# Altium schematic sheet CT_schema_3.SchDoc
size 362 x 192 mm
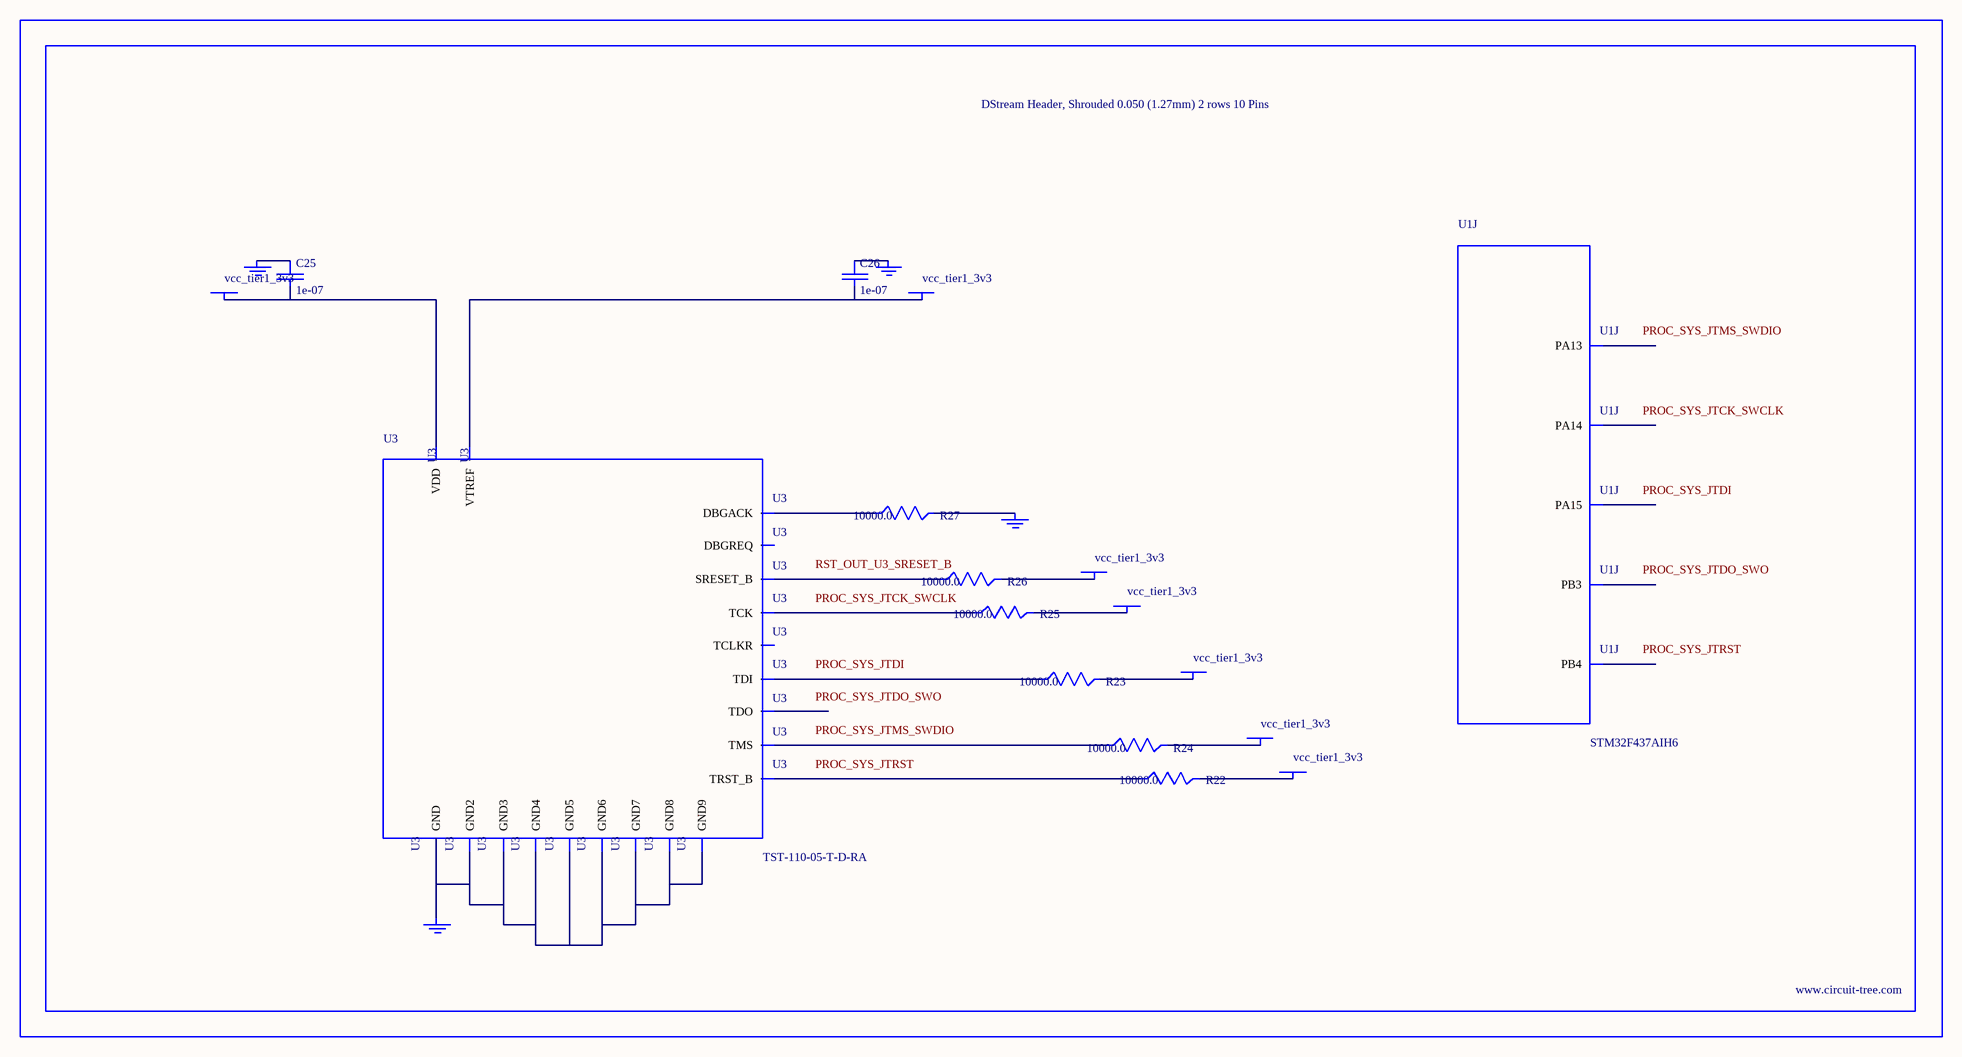
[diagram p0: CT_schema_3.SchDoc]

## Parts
BORDER2  (no value)
C25  1e-07  [C0402]
C26  1e-07  [C0402]
GND_INSTANCE_2_0  (no value)
GND_INSTANCE_2_1  (no value)
GND_INSTANCE_2_2  (no value)
GND_INSTANCE_2_3  (no value)
POWER_INSTANCE_2_0  vcc_tier1_3v3
POWER_INSTANCE_2_1  vcc_tier1_3v3
POWER_INSTANCE_2_2  vcc_tier1_3v3
POWER_INSTANCE_2_3  vcc_tier1_3v3
POWER_INSTANCE_2_4  vcc_tier1_3v3
POWER_INSTANCE_2_5  vcc_tier1_3v3
POWER_INSTANCE_2_6  vcc_tier1_3v3
R22  10000.0  [R0603]
R23  10000.0  [R0603]
R24  10000.0  [R0603]
R25  10000.0  [R0603]
R26  10000.0  [R0603]
R27  10000.0  [R0603]
U1  STM32F437AIH6  [UFBGA169]  (part J of 12)
U3  TST-110-05-T-D-RA  [TST-110-05-T-D-RA]

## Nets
NetC25_1: C25.1 GND_INSTANCE_2_1.0(GND)
NetC25_2: C25.2 POWER_INSTANCE_2_1.0(PWR) U3.2(VDD)
NetC26_1: C26.1 GND_INSTANCE_2_0.0(GND)
NetC26_2: C26.2 POWER_INSTANCE_2_0.0(PWR) U3.1(VTREF)
NetGND_INSTANCE_2_2_0: GND_INSTANCE_2_2.0(GND) R27.2
NetGND_INSTANCE_2_3_0: GND_INSTANCE_2_3.0(GND) U3.4(GND) U3.6(GND2) U3.8(GND3) U3.10(GND4) U3.12(GND5) U3.14(GND6) U3.16(GND7) U3.18(GND8) U3.20(GND9)
NetPOWER_INSTANCE_2_2_0: POWER_INSTANCE_2_2.0(PWR) R22.2
NetPOWER_INSTANCE_2_3_0: POWER_INSTANCE_2_3.0(PWR) R23.2
NetPOWER_INSTANCE_2_4_0: POWER_INSTANCE_2_4.0(PWR) R24.2
NetPOWER_INSTANCE_2_5_0: POWER_INSTANCE_2_5.0(PWR) R25.2
NetPOWER_INSTANCE_2_6_0: POWER_INSTANCE_2_6.0(PWR) R26.2
NetR22_1: R22.1 U3.3(TRST_B)
NetR23_1: R23.1 U3.5(TDI)
NetR24_1: R24.1 U3.7(TMS)
NetR25_1: R25.1 U3.9(TCK)
NetR26_1: R26.1 U3.15(SRESET_B)
NetR27_1: R27.1 U3.19(DBGACK)

Not connected (* = marked no-connect by the designer): U1 A6(PB4) A11(PA14) B6(PB3) B11(PA15) E12(PA13); U3 11(TCLKR) 13(TDO) 17(DBGREQ)

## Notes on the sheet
- Labels drawn without touching a wire or pin: PROC_SYS_JTCK_SWCLK, PROC_SYS_JTDI, PROC_SYS_JTDO_SWO, PROC_SYS_JTMS_SWDIO, PROC_SYS_JTRST, RST_OUT_U3_SRESET_B

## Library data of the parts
BORDER2 = BORDER_PAGE2
C25 C26 = C0402C104K3RACTU
GND_INSTANCE_2_0-GND_INSTANCE_2_3 = GND
POWER_INSTANCE_2_0-POWER_INSTANCE_2_6 = PWR
R22-R27 = RC0603JR-0710KL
